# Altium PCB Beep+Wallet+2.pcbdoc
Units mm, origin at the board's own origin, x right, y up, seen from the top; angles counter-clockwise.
Board outline 180.01 x 75.63 mm, 2 copper layers (Top Layer, Bottom Layer); 63 components, 77 nets, 190 pads, 31 vias.
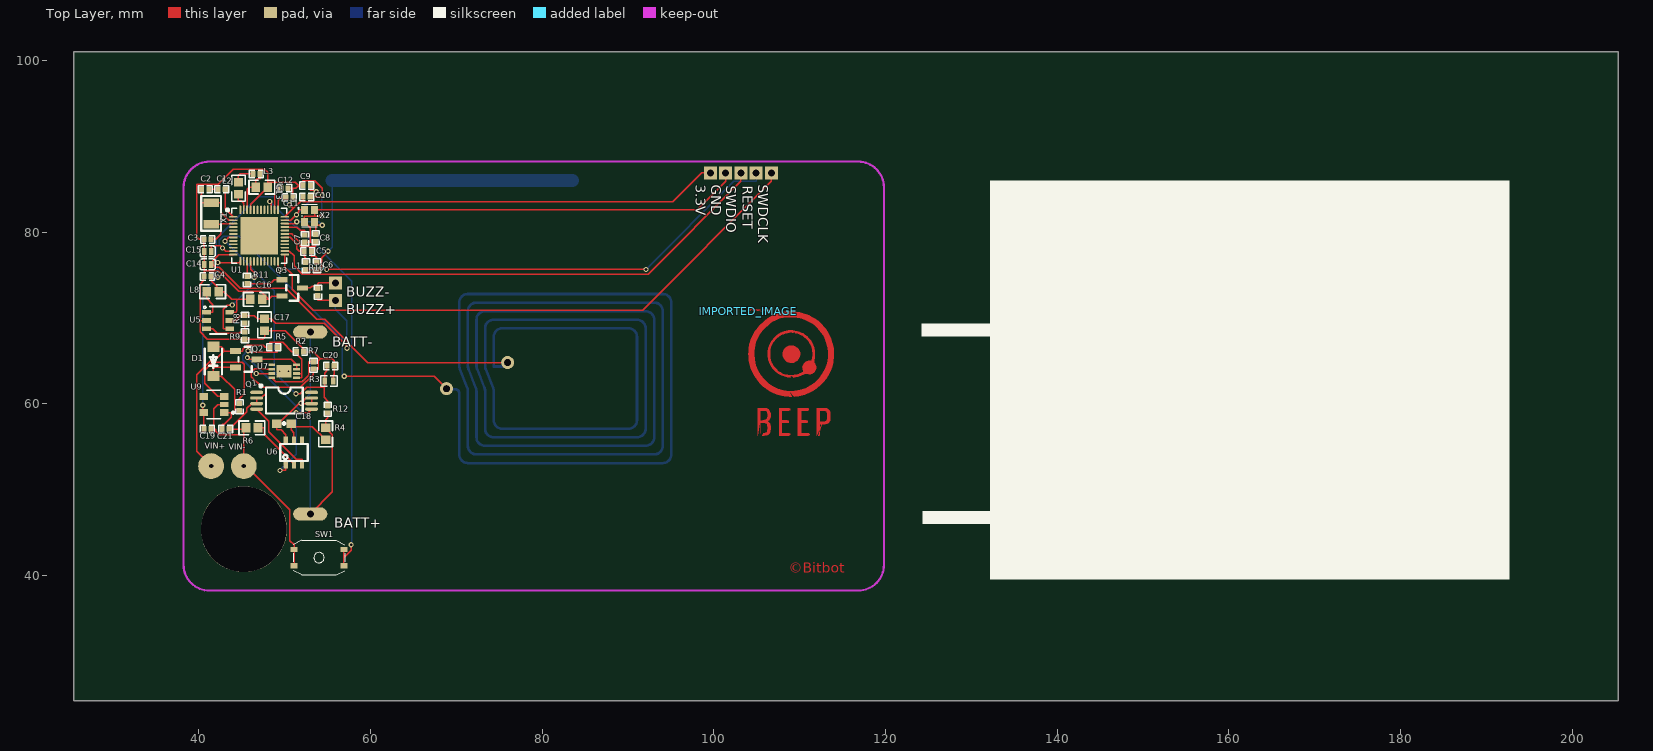
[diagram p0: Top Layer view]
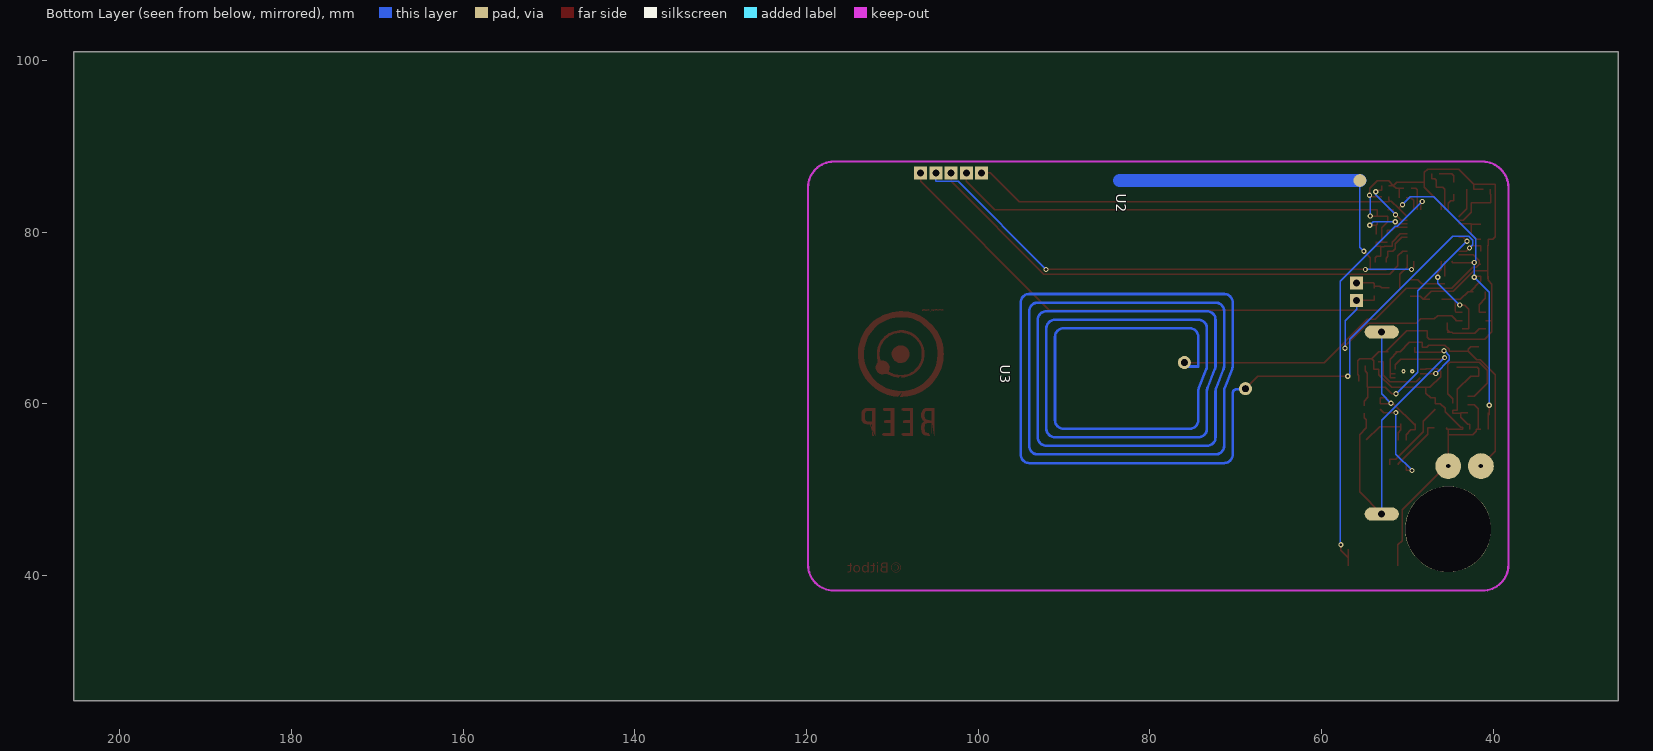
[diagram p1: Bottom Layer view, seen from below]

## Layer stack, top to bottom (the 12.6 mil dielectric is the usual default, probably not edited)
Top Layer: signal copper (thickness not stored)
Dielectric: dielectric 0.32, FR-4, Dk 4.8
Bottom Layer: signal copper (thickness not stored)

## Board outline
205.411,25.4 25.4,25.4 25.4,101.034 205.411,101.034

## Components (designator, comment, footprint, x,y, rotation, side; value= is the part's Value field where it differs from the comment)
3.3V "Pad 04" CON_PAD_SQUARE_32MIL#1 99.596,86.896 r0 top
BATT+ "Pad 09" CON_PAD_SQUARE_32MIL#2 52.987,47.145 r0 top
BATT- "Pad 08" CON_PAD_SQUARE_32MIL#2 52.987,68.354 r0 top
BUZZ+ "Pad 06" CON_PAD_SQUARE_32MIL#1 55.908,72.037 r180 top
BUZZ- "Pad 07" CON_PAD_SQUARE_32MIL#1 55.908,74.069 r180 top
C1 "100nF" 0402 42.657,84.991 r0 top
C2 "12pF" 0402 40.752,84.991 r0 top
C3 "12pF" 0402 41.006,79.149 r180 top
C4 "100nF" 0402 41.006,74.831 r0 top
C5 "0.8pF" 0402 52.69,77.752 r180 top
C6 "1.2pF" 0402 53.749,76.058 r90 top
C7 "100pF" 0402 52.352,79.233 r270 top
C8 "12pF" 0402 53.622,79.319 r90 top
C9 "12pF" 0402 52.578,85.42 r0 top
C10 "100nF" 0402 52.563,84.102 r0 top
C11 "12pF" 0402 50.546,84.023 r180 top
C12 "12pF" 0402 49.982,85.118 r180 top
C13 "1uF" 0603#1 47.334,85.245 r0 top
C14 "300pF" CAP_0402 41.03,76.228 r180 top
C15 "300pF" CAP_0402 41.03,77.752 r0 top
C16 "4.7uF" 0603#1 46.699,72.164 r0 top
C17 "4.7uF" 0603#1 47.653,69.178 r270 top
C18 "0.1UF-25V-5%(0603)" 0603-CAP 49.939,57.686 r0 top
C19 "10pF" 0402 41.006,57.051 r0 top
C20 "10nF" 0402 55.357,64.417 r0 top
C21 "10pF" 0402 43.124,57.051 r0 top
D1 "LMBR120FT1G" SOD-123_L2.8-W1.8-LS3.7-RD 41.684,64.925 r90 top
GND "Pad 05" CON_PAD_SQUARE_32MIL#1 101.374,86.896 r0 top
IMPORTED_IMAGE "IMPORTED_IMAGE" IMPORTED_IMAGE 104.041,70.767 r0 top
L1 "3.9nH" 0402 52.479,76.058 r270 top
L2 "10uH" 0603#1 44.62,85.104 r90 top
L3 "15nH" 0402 46.721,86.769 r0 top
L8 "10uH" 0603#1 41.619,73.053 r0 top
Q1 "FS8205A" TSSOP-8_3X4.4X065P 47.145,61.369 r0 top
Q2 "DMG3415U-7" SOT-23-3_L2.9-W1.6-P1.90-LS2.8-BR-CW 45.515,65.179 r180 top
Q3 "PMBT3904,215" SOT-23_L2.9-W1.3-P0.95-LS2.4-BR 50.885,73.495 r180 top
R1 "100K" 0402 44.732,59.634 r270 top
R2 "100K" 0402 51.801,66.068 r180 top
R3 "4.02M" R0402 55.154,62.639 r0 top
R4 "100Ω(100R)" 0603#2 54.765,55.681 r90 top
R5 "1K" 0402 48.712,66.576 r0 top
R6 "1KΩ" 0603#2 45.391,57.178 r0 top
R7 "1K" 0402 53.368,64.46 r270 top
R8 "1M" 0402 45.367,69.835 r270 top
R9 "29.4K" 0402 45.367,67.93 r90 top
R10 "3.01K" 0402 53.876,73.01 r90 top
R11 "10K" 0402 45.621,74.407 r270 top
R12 "10M" 0402 55.019,59.337 r90 top
RESET "Pad 03" CON_PAD_SQUARE_32MIL#1 104.93,86.896 r0 top
SW1 "SKTKABE010" SKTKABE010 54.003,42.065 r0 top
SWDCLK "Pad 02" CON_PAD_SQUARE_32MIL#1 106.708,86.896 r0 top
SWDIO "Pad 01" CON_PAD_SQUARE_32MIL#1 103.152,86.896 r0 top
U1 "2.4GHz" QFN-48_L6.0-W6.0-P0.40-BL-EP3.8 47.033,79.578 r270 top
U2 "Antenna" ANTENNA 62.639,86.007 r270 bottom
U3 "NFC_Antenna" NFC_ANTENNA 79.784,61.496 r270 bottom
U5 "TLV61046ADBVT" SOT-23-6#1 42.239,69.69 r0 top
U6 "DW01A-G" SOT-23-6#2 51.082,54.308 r0 top
U7 "MCP73831-2ACI/MC" DFN-MC8 49.939,63.782 r180 top
U9 "AP2112K-3.3TRG1" SOT-25_5PIN_L3.10-W3.00-PITCH0.95-BR 41.754,59.906 r0 top
VIN+ "Pad 10" CON_PAD_SQUARE_32MIL#3 41.43,52.733 r0 top
VIN- "Pad 11" CON_PAD_SQUARE_32MIL#3 45.24,52.733 r0 top
X1 "32.768MHz" OSC-SMD_L3.2-W1.5 41.43,82.177 r270 top
X2 "32MHz" OSC-SMD_4P-L2.0-W1.6-BL 52.895,81.878 r270 top

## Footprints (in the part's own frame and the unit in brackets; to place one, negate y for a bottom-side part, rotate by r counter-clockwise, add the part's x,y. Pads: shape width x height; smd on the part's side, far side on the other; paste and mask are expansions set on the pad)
0402 [mm]
  rect 0.6x0.65 smd: 1(-0.424,0) 2(0.424,0)
  silkscreen extent -0.82,-0.43 0.81,0.43
0603#1 [mm]
  rect 1x1.1 smd: 1(-0.7,0) 2(0.7,0)
  silkscreen extent -1.5,-0.8 1.5,0.8
0603#2 [mm]
  rect 1x1.1 smd: 1(0.1,0) 2(1.5,0)
  silkscreen extent -0.7,-0.8 2.3,0.8
0603-CAP [mil]
  rect 43.3x39.4 smd: 1(-33,0) 2(33,0)
  silkscreen extent 0,-1 0,1
ANTENNA [mm]
  round 1.5 smd: 1(0,7.112)
  Top Layer lines w1.5: 0,7.112 0,-20.888
CAP_0402 [mm]
  rect 0.5x0.8 smd: 1(-0.4,0) 2(0.4,0)
  silkscreen extent -0.89,-0.64 0.89,0.64
CON_PAD_SQUARE_32MIL#1 [mil]
  rect 60x60 hole 32: P(0,0)
CON_PAD_SQUARE_32MIL#2 [mil]
  oval 157.48x60 hole 32: P(0,0)
CON_PAD_SQUARE_32MIL#3 [mil]
  round 118.11 hole 19.69: P(0,0)
DFN-MC8 [mil]
  rect 30.5x12.5 smd: 1(-57,29.5) 2(-57,10.5) 3(-57,-9.5) 4(-57,-29.5) 5(57,-29.5) 6(57,-9.5) 7(57,10.5) 8(57,29.5)
  rect 69.5x57.5 smd: 9(0,0.5)
  silkscreen extent -82,44 -82,44
IMPORTED_IMAGE [mm]
  Top Layer region: 1.091,-14.489 1.091,-12.893 1.091,-11.297 1.617,-11.297 1.703,-11.298 1.788,-11.299 1.871,-11.302 1.949,-11.306 2.022,-11.31 2.088,-11.315 2.146,-11.321 2.194,-11.327 2.232,-11.334 2.258,-11.341 2.351,-11.402 2.43,-11.501 2.494,-11.631 2.542,-11.782 2.571,-11.947 2.583,-12.116 2.574,-12.281 2.545,-12.433 2.494,-12.564 2.42,-12.666 2.261,-12.822 2.42,-12.979 2.456,-13.017 2.487,-13.055 2.512,-13.096 2.533,-13.139 2.549,-13.188 2.561,-13.243 2.57,-13.306 2.576,-13.379 2.579,-13.464 2.58,-13.561 2.574,-13.772 2.555,-13.95 2.52,-14.098 2.465,-14.217 2.389,-14.311 2.288,-14.382 2.16,-14.432 2.002,-14.465 1.811,-14.483 1.584,-14.489 1.715,-14.205 1.771,-14.204 1.826,-14.201 1.88,-14.195 1.932,-14.188 1.98,-14.18 2.024,-14.17 2.063,-14.159 2.096,-14.147 2.122,-14.134 2.14,-14.12 2.154,-14.1 2.167,-14.071 2.18,-14.033 2.191,-13.987 2.201,-13.934 2.209,-13.875 2.216,-13.812 2.221,-13.744 2.224,-13.674 2.225,-13.602 2.224,-13.53 2.221,-13.46 2.216,-13.393 2.209,-13.329 2.201,-13.27 2.191,-13.217 2.18,-13.171 2.167,-13.133 2.154,-13.104 2.14,-13.084 2.122,-13.071 2.096,-13.057 2.063,-13.045 2.024,-13.034 1.98,-13.024 1.932,-13.016 1.88,-13.009 1.826,-13.004 1.771,-13 1.715,-12.999 1.374,-12.999 1.374,-13.602 1.374,-14.205 1.374,-12.734 1.693,-12.698 1.746,-12.691 1.799,-12.682 1.852,-12.672 1.902,-12.66 1.95,-12.647 1.994,-12.633 2.034,-12.618 2.069,-12.603 2.097,-12.588 2.119,-12.574 2.155,-12.525 2.183,-12.45 2.205,-12.354 2.219,-12.243 2.225,-12.126 2.224,-12.008 2.215,-11.897 2.198,-11.798 2.173,-11.719 2.14,-11.666 2.122,-11.652 2.096,-11.639 2.063,-11.627 2.024,-11.616 1.98,-11.606 1.932,-11.597 1.88,-11.59 1.826,-11.585 1.771,-11.582 1.715,-11.581 1.374,-11.581 1.374,-12.157 1.374,-12.734
  Top Layer region: 3.573,-14.489 3.573,-12.893 3.573,-11.297 4.211,-11.297 4.373,-11.298 4.504,-11.299 4.61,-11.303 4.691,-11.309 4.752,-11.319 4.795,-11.332 4.823,-11.35 4.84,-11.374 4.847,-11.403 4.849,-11.439 4.848,-11.474 4.841,-11.503 4.827,-11.526 4.804,-11.544 4.77,-11.558 4.722,-11.568 4.658,-11.574 4.577,-11.578 4.476,-11.58 4.353,-11.581 3.856,-11.581 3.856,-12.148 3.856,-12.716 4.282,-12.716 4.386,-12.716 4.472,-12.718 4.541,-12.722 4.595,-12.729 4.637,-12.739 4.667,-12.753 4.687,-12.771 4.7,-12.794 4.706,-12.823 4.708,-12.857 4.706,-12.892 4.7,-12.921 4.687,-12.944 4.667,-12.962 4.637,-12.976 4.595,-12.986 4.541,-12.992 4.472,-12.997 4.386,-12.999 4.282,-12.999 3.856,-12.999 3.856,-13.602 3.856,-14.205 4.353,-14.205 4.476,-14.205 4.577,-14.207 4.658,-14.211 4.722,-14.218 4.77,-14.228 4.804,-14.241 4.827,-14.259 4.841,-14.283 4.848,-14.312 4.849,-14.347 4.847,-14.383 4.84,-14.412 4.823,-14.435 4.795,-14.453 4.752,-14.467 4.691,-14.476 4.61,-14.483 4.504,-14.486 4.373,-14.488 4.211,-14.489
  Top Layer region: 5.771,-14.489 5.771,-12.893 5.771,-11.297 6.41,-11.297 6.571,-11.298 6.703,-11.299 6.808,-11.303 6.89,-11.309 6.95,-11.319 6.994,-11.332 7.022,-11.35 7.038,-11.374 7.046,-11.403 7.048,-11.439 7.046,-11.474 7.04,-11.503 7.027,-11.526 7.005,-11.544 6.973,-11.558 6.928,-11.567 6.869,-11.574 6.794,-11.578 6.7,-11.58 6.587,-11.581 6.126,-11.581 6.126,-12.148 6.126,-12.716 6.516,-12.716 6.61,-12.716 6.688,-12.718 6.751,-12.723 6.801,-12.73 6.84,-12.74 6.868,-12.754 6.887,-12.772 6.898,-12.795 6.904,-12.823 6.906,-12.857 6.904,-12.892 6.898,-12.92 6.887,-12.943 6.868,-12.961 6.84,-12.975 6.801,-12.985 6.751,-12.992 6.688,-12.996 6.61,-12.999 6.516,-12.999 6.126,-12.999 6.126,-13.602 6.126,-14.205 6.622,-14.205 6.745,-14.205 6.847,-14.207 6.928,-14.211 6.991,-14.218 7.039,-14.228 7.074,-14.241 7.097,-14.259 7.11,-14.283 7.117,-14.312 7.119,-14.347 7.117,-14.383 7.109,-14.412 7.092,-14.436 7.062,-14.454 7.017,-14.467 6.953,-14.477 6.867,-14.483 6.756,-14.486 6.616,-14.488 6.445,-14.489
  Top Layer region: 7.97,-14.489 7.97,-12.893 7.97,-11.297 8.576,-11.297 8.727,-11.298 8.853,-11.3 8.957,-11.305 9.042,-11.313 9.113,-11.325 9.172,-11.342 9.222,-11.364 9.267,-11.393 9.311,-11.428 9.356,-11.471 9.399,-11.516 9.434,-11.559 9.463,-11.604 9.485,-11.654 9.502,-11.711 9.514,-11.778 9.522,-11.86 9.527,-11.959 9.53,-12.077 9.53,-12.219 9.53,-12.361 9.527,-12.479 9.522,-12.578 9.514,-12.66 9.502,-12.727 9.485,-12.784 9.463,-12.834 9.434,-12.879 9.399,-12.922 9.356,-12.967 9.313,-13.007 9.272,-13.041 9.23,-13.069 9.185,-13.092 9.135,-13.109 9.079,-13.122 9.015,-13.131 8.94,-13.137 8.854,-13.14 8.753,-13.141 8.325,-13.141 8.325,-13.815 8.324,-13.997 8.323,-14.143 8.32,-14.256 8.313,-14.342 8.302,-14.403 8.286,-14.445 8.263,-14.47 8.234,-14.483 8.195,-14.488 8.147,-14.489 8.665,-12.857 8.721,-12.856 8.777,-12.853 8.831,-12.848 8.882,-12.841 8.93,-12.832 8.974,-12.822 9.013,-12.811 9.046,-12.799 9.072,-12.786 9.091,-12.772 9.105,-12.752 9.118,-12.722 9.131,-12.682 9.142,-12.634 9.151,-12.578 9.16,-12.516 9.167,-12.448 9.171,-12.375 9.175,-12.299 9.176,-12.219 9.175,-12.139 9.171,-12.063 9.167,-11.99 9.16,-11.922 9.151,-11.86 9.142,-11.804 9.131,-11.756 9.118,-11.716 9.105,-11.686 9.091,-11.666 9.072,-11.652 9.046,-11.639 9.013,-11.627 8.974,-11.616 8.93,-11.606 8.882,-11.597 8.831,-11.59 8.777,-11.585 8.721,-11.582 8.665,-11.581 8.325,-11.581 8.325,-12.219 8.325,-12.857 8.665,-12.857
  Top Layer region: 162 vertices and 0 holes, not listed, extent 0,-9.947 9.946,-0.002
  Top Layer region: 214 vertices and 0 holes, not listed, extent 2.24,-7.729 7.892,-2.216
  Top Layer region: 5.056,-6.017 4.947,-6.012 4.835,-5.993 4.721,-5.961 4.603,-5.915 4.49,-5.858 4.388,-5.793 4.297,-5.719 4.219,-5.637 4.152,-5.547 4.097,-5.45 4.054,-5.345 4.024,-5.232 4.005,-5.112 3.999,-4.985 4.004,-4.879 4.018,-4.777 4.042,-4.679 4.076,-4.586 4.118,-4.497 4.17,-4.413 4.231,-4.334 4.302,-4.26 4.381,-4.191 4.469,-4.127 4.509,-4.103 4.552,-4.082 4.6,-4.062 4.65,-4.045 4.704,-4.029 4.759,-4.017 4.816,-4.007 4.875,-3.999 4.933,-3.994 4.991,-3.993 5.266,-4.025 5.504,-4.114 5.703,-4.252 5.858,-4.428 5.966,-4.633 6.023,-4.857 6.026,-5.091 5.97,-5.324 5.853,-5.548 5.669,-5.752 5.57,-5.831 5.471,-5.896 5.37,-5.947 5.267,-5.984 5.163,-6.007
NFC_ANTENNA [mil]
  round 60 hole 30 slot 30.2 at 0 deg: 1(-10,430) 2(-130,150)
  Top Layer lines w11.81: -12.07,427.81 cw(c-24.99,414.89) -6.72,414.9 -6.72,414.31 -6.72,392.82 -6.72,389.05 ccw(c11,389.05) 11,371.33 289.74,371.33 291.72,371.33 cw(c291.72,331.97) 331.08,331.97 331.08,-561.74 cw(c291.72,-561.74) 291.72,-601.1 -405.14,-601.11 cw(c-405.14,-561.74) -444.51,-561.74 -444.51,331.97 cw(c-405.15,331.97) -405.15,371.33 -114.19,371.33 -113.15,371.33 -110.41,371.16 -107.69,370.8 -104.99,370.25 -102.35,369.52 -99.76,368.6 -13.67,334.7 ; -13.99,334.84 ccw(c0.77,371.34) 0.76,331.97 252.34,331.97 cw(c252.34,292.6) 291.71,292.6 291.71,-522.37 ; -13.99,295.46 ccw(c0.77,331.96) 0.76,292.59 212.97,292.59 cw(c212.97,253.22) 252.34,253.22 252.34,-483 cw(c212.97,-482.99) 212.97,-522.36 ; -13.67,295.33 -99.76,329.23 -102.35,330.15 -104.99,330.88 -107.69,331.43 -110.41,331.79 -113.15,331.96 -114.19,331.97 -365.77,331.97 ccw(c-365.77,292.6) -405.14,292.6 ; -13.99,256.09 ccw(c0.77,292.59) 0.76,253.22 173.6,253.22 cw(c173.6,213.85) 212.97,213.85 212.97,-443.63 cw(c173.6,-443.62) 173.6,-482.99 -287.03,-483 cw(c-287.03,-443.63) -326.4,-443.63 -326.4,213.85 cw(c-287.03,213.85) -287.03,253.22 -114.19,253.22 -113.15,253.22 -110.41,253.05 -107.69,252.69 -104.99,252.14 -102.35,251.41 -99.76,250.49 -13.67,216.59 ; -13.67,255.96 -99.76,289.86 -102.35,290.78 -104.99,291.51 -107.69,292.06 -110.41,292.42 -113.15,292.59 -114.19,292.59 -326.4,292.59 ccw(c-326.4,253.22) -365.77,253.22 -365.77,-483 ccw(c-326.4,-483) -326.4,-522.37 212.97,-522.37 ; -13.99,216.72 ccw(c0.77,253.22) 0.76,213.85 134.23,213.85 cw(c134.23,174.48) 173.6,174.48 173.6,-404.26 cw(c134.23,-404.25) 134.23,-443.62 -247.66,-443.63 cw(c-247.66,-404.26) -287.03,-404.26 -287.03,174.48 cw(c-247.66,174.48) -247.66,213.85 -111.83,213.85 -111.83,168.17 -130,150 ; 291.71,-522.36 291.71,-522.37 ; -405.14,292.6 -405.14,292.59 ; -405.14,292.59 -405.14,-522.37 ccw(c-365.77,-522.37) -365.77,-561.74 252.34,-561.74 ccw(c252.34,-522.37) 291.71,-522.37
OSC-SMD_4P-L2.0-W1.6-BL [mm]
  rect 0.9x0.8 smd: 1(-0.7,-0.6) 2(0.7,-0.6) 3(0.7,0.6) 4(-0.7,0.6)
  silkscreen extent -1.3,-1.37 1.3,0.9
OSC-SMD_L3.2-W1.5 [mm]
  rect 1x1.8 smd: 1(-1.25,0) 2(1.25,0)
  silkscreen extent -2.03,-1.14 2.03,1.14
QFN-48_L6.0-W6.0-P0.40-BL-EP3.8 [mm]
  oval 0.22x1 smd: 1(-2.201,-3) 2(-1.8,-3) 3(-1.401,-3) 4(-0.999,-3) 5(-0.601,-3) 6(-0.199,-3) 7(0.199,-3) 8(0.601,-3) 9(0.999,-3) 10(1.401,-3) 11(1.8,-3) 12(2.201,-3) 25(2.201,3) 26(1.8,3) 27(1.401,3) 28(0.999,3) 29(0.601,3) 30(0.199,3) 31(-0.199,3) 32(-0.601,3) 33(-0.999,3) 34(-1.401,3) 35(-1.8,3) 36(-2.201,3)
  oval 1x0.22 smd: 13(3,-2.198) 14(3,-1.8) 15(3,-1.401) 16(3,-0.999) 17(3,-0.601) 18(3,-0.199) 19(3,0.199) 20(3,0.601) 21(3,0.999) 22(3,1.401) 23(3,1.8) 24(3,2.201) 37(-3,2.201) 38(-3,1.8) 39(-3,1.401) 40(-3,0.999) 41(-3,0.601) 42(-3,0.199) 43(-3,-0.199) 44(-3,-0.601) 45(-3,-0.999) 46(-3,-1.401) 47(-3,-1.8) 48(-3,-2.198)
  rect 4.4x4.4 smd: 49(-0.001,0.001)
  silkscreen extent -3.2,-3.85 3.2,3.2
R0402 [mm]
  rect 0.5x0.8 smd: 1(-0.5,0) 2(0.5,0)
  silkscreen extent -0.95,-0.6 0.95,0.6
SKTKABE010 [mm]
  rect 0.8x0.6 smd: 1(-2.9,0.95) 2(-2.9,-0.95) 3(2.9,-0.95) 4(2.9,0.95)
  silkscreen extent -3,-2 3,2
SOD-123_L2.8-W1.8-LS3.7-RD [mm]
  rect 1.2x1.4 smd: 1(-1.7,0) 2(1.7,0)
  silkscreen extent -1.5,-1 1.5,1
SOT-23-3_L2.9-W1.6-P1.90-LS2.8-BR-CW [mm]
  rect 1.25x0.7 smd: 1(1.25,-0.95) 2(-1.25,0) 3(1.25,0.95)
  silkscreen extent -0.65,-1.46 0.9,1.46
SOT-23-6#1 [mm]
  rect 1x0.55 smd: 1(-1.35,0.95) 2(-1.35,0) 3(-1.35,-0.95) 4(1.35,-0.95) 5(1.35,0) 6(1.35,0.95)
  silkscreen extent -1.67,-1.56 1.01,1.67
SOT-23-6#2 [mm]
  rect 0.511x0.8 smd: 1(-0.94,-1.448) 2(0,-1.448) 3(0.94,-1.448) 4(0.94,1.448) 5(0,1.448) 6(-0.94,1.448)
  silkscreen extent -1.6,-0.99 1.6,0.99
SOT-23_L2.9-W1.3-P0.95-LS2.4-BR [mm]
  rect 1.3x0.6 smd: 1(1.2,-0.95) 2(1.2,0.95) 3(-1.2,0)
  silkscreen extent -0.7,-1.5 0.7,1.5
SOT-25_5PIN_L3.10-W3.00-PITCH0.95-BR [mm]
  rect 1x0.8 smd: 1(1.2,-0.95) 3(1.2,0.95) 4(-1.2,0.95) 5(-1.2,-0.95)
  rect 1x0.6 smd: 2(1.2,0)
  silkscreen extent -0.8,-1.65 2.38,1.65
TSSOP-8_3X4.4X065P [mm]
  oval 1.5x0.4 smd: 1(-0.406,-0.051) 2(-0.406,-0.701) 3(-0.406,-1.351) 4(-0.406,-2.002) 5(5.994,-2.002) 6(5.994,-1.351) 7(5.994,-0.701) 8(5.994,-0.051)
  silkscreen extent -0.07,-2.51 4.95,0.86

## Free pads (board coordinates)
  round 10 hole 10 unplated: ""(45.24,45.367)

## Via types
v1: diameter 0.61, hole 0.31, Top Layer to Bottom Layer, 29 vias
v2: diameter 0.5, hole 0.201, Top Layer to Bottom Layer, 2 vias

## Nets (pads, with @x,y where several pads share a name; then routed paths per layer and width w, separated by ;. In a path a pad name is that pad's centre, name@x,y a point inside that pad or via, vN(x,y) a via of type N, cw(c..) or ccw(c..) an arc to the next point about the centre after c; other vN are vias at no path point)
3.3V: 3.3V.P C4.2 C10.1 C16.1 C19.1 L8.2 U1.13 U1.36 U5.6 U9.5 | length 99.4
  Top Layer w0.16: v1(40.452,59.832) 40.452,58.735 U9.5@40.554,58.634 ; U9.5 U9.5@40.554,58.634 ; C19.1 40.582,58.286 40.554,58.313 U9.5@40.554,58.634 ; v1(42.205,74.73) 42.103,74.831 41.974,74.831 C4.2 41.43,74.265 41.478,74.265 L8.2@42.69,73.053 ; v1(42.205,76.444) 44.694,76.444 U1.13@44.836,76.586 ; L8.2 L8.2@42.69,73.053 ; U5.6 44.331,70.64 44.443,70.752 44.443,72.164 ; C16.1 44.443,72.164 ; U1.36@50.026,81.778 50.998,82.751 ; v1(50.572,83.178) 50.998,82.751 ; C10.1 52.139,83.769 52.08,83.711 52.08,83.609 ; 3.3V.P 98.593,86.896 95.212,83.515 52.174,83.515 52.08,83.609 ; L8.2@42.69,73.053 42.929,73.053 43.818,72.164 44.443,72.164 ; 50.998,82.751 51.857,83.609 52.08,83.609
  Bottom Layer w0.16: v1(40.452,59.832) 40.452,72.977 v1(42.205,74.73) v1(42.205,76.444) 42.012,76.637 42.012,79.192 46.929,84.11 49.639,84.11 v1(50.572,83.178)
BAT: C20.1 R3.1 R12.2 U1.7 | length 30.9
  Top Layer w0.16: v1(43.053,78.928) 43.503,79.378 U1.7@44.026,79.378 ; v1(51.313,61.168) 51.814,61.168 52.578,61.93 54.59,61.93 ; C20.1 54.933,64.133 54.933,63.851 54.653,63.571 R3.1 54.653,62.012 54.653,61.996 54.59,61.93 ; R12.2 55.019,60.302 54.59,60.734 54.59,61.93
  Bottom Layer w0.16: v1(43.053,78.928) 48.801,73.18 48.801,63.681 v1(51.313,61.168)
BUTTON: SW1.3 SW1.4 U1.39 | length 48.9
  Top Layer w0.16: v1(48.268,83.564) 48.436,83.396 U1.39@48.436,82.586 ; SW1.3 56.904,42.065 ; SW1.4 56.904,42.065 ; v1(57.74,43.564) 57.74,42.903 56.904,42.065
  Bottom Layer w0.16: v1(48.268,83.564) 51.169,80.663 51.387,80.663 57.808,74.242 57.808,43.63 v1(57.74,43.564)
BUZZ: R11.1 U1.15 | length 1.8
  Top Layer w0.16: R11.1 45.621,75.372 45.634,75.385 U1.15@45.634,76.586
BUZZ+: BUZZ+.P C17.1 R8.1 R10.1 U5.5 | length 24.4
  Top Layer w0.16: U5.5 44.331,69.69 44.331,69.792 44.801,70.259 R8.1 46.48,70.259 46.861,69.878 C17.1 48.446,69.878 48.944,69.38 54.628,69.38 57.259,66.746 v1(57.259,66.472) ; R10.1 53.876,72.042 53.884,72.037 BUZZ+.P
  Bottom Layer w0.16: BUZZ+.P 55.908,71.034 57.259,69.68 v1(57.259,66.472)
BUZZ-: BUZZ-.P Q3.3 R10.2 | length 4.5
  Top Layer w0.16: Q3.3 52.977,73.495 53.188,73.706 R10.2@53.876,73.706 ; R10.2 R10.2@53.876,73.706 ; BUZZ-.P 53.97,74.069 53.876,73.975 R10.2@53.876,73.706
BUZZEN: U1.16 U5.4 | length 10.6
  Top Layer w0.16: U5.4 42.848,68.74 42.848,71.013 43.33,71.499 v1(43.897,71.499) ; U1.16@46.035,76.586 46.035,75.679 46.449,75.263 v1(46.449,74.742)
  Bottom Layer w0.16: v1(43.897,71.499) 46.449,74.054 v1(46.449,74.742)
GND: C1.1 C2.2 C3.2 C4.1 C5.1 C6.2 C7.2 C8.1 C9.1 C10.2 C11.1 C12.1 C13.2 C14.2 C15.1 C16.2 C17.2 C19.2 C20.2 C21.2 GND.P Q1.2 Q1.3 Q3.2 R2.1 R3.2 R6.1 R7.2 R9.1 SW1.1 SW1.2 U1.31 U1.45 U5.2 U7.6 U9.2 VIN-.P X2.2 X2.4 | length 197.2
  Top Layer w0.16: C4.1 C4.1@40.582,74.547 ; U5.2 40.147,69.69 ; C2.2 C1.1 42.233,85.558 ; C19.2 41.743,57.051 ; U9.2 42.213,59.906 41.743,59.436 41.743,57.051 ; R6.1 45.365,57.051 R6.1@45.24,57.051 ; U1.45@46.035,82.586 46.035,83.246 C13.2 48.034,85.827 ; C16.2 48.141,72.164 ; U7.6 47.861,64.023 47.803,64.084 46.49,64.084 46.134,63.729 46.134,63.147 47.386,61.895 47.861,61.895 ; Q3.2 48.522,72.545 48.141,72.164 ; U1.31@50.026,79.776 50.828,79.776 51.786,78.821 51.786,78.367 51.834,78.319 52.667,78.319 52.69,78.293 53.114,78.293 ; C12.1 50.678,85.118 50.97,85.118 ; C11.1 50.97,84.308 50.97,84.59 50.97,85.118 ; SW1.2 SW1.1 51.103,43.556 50.605,44.056 50.605,47.653 45.525,52.733 VIN-.P 45.24,56.388 ; C9.1 51.613,85.42 ; R2.1 R2.1@52.497,66.068 ; C7.2 52.987,78.809 ; C10.2 53.531,84.102 54.204,84.102 v1(54.405,84.3) 54.405,85.103 53.521,85.987 52.179,85.987 51.613,85.42 ; C8.1 C8.1@53.622,78.809 ; C6.2 53.749,77.023 53.589,77.186 53.114,77.186 C5.1 53.114,78.037 53.114,78.237 53.114,78.293 ; v1(54.321,81.869) 53.495,81.869 ; R3.2 55.654,63.282 55.781,63.409 C20.2 55.781,64.984 55.55,65.215 54.166,65.215 ; GND.P 101.374,85.893 98.059,82.578 X2.4 53.495,81.869 ; 40.147,69.69 40.147,73.922 40.582,74.359 C4.1@40.582,74.547 ; 40.147,69.69 40.147,68.364 41.006,67.506 R9.1 47.422,67.506 47.653,67.737 C17.2 50.087,68.479 R2.1@52.497,66.068 ; C4.1@40.582,74.547 40.63,74.595 40.63,75.492 ; 40.63,75.492 42.248,75.492 44.623,73.117 47.188,73.117 48.141,72.164 ; 40.63,75.492 C14.2 C15.1 40.63,78.395 40.582,78.443 C3.2 40.041,79.149 39.749,79.441 39.749,85.512 39.794,85.558 42.233,85.558 ; 41.743,57.051 41.974,57.051 41.974,56.779 42.365,56.388 45.24,56.388 ; 42.233,85.558 44.011,87.336 47.64,87.336 48.034,86.944 48.034,85.827 ; 45.24,56.388 R6.1@45.24,57.051 ; R6.1@45.24,57.051 C21.2 43.549,57.262 43.782,57.262 45.601,59.081 45.601,59.446 46.175,60.018 Q1.3 Q1.2 47.282,60.668 47.861,61.247 47.861,61.895 ; 47.861,61.895 51.829,61.895 53.307,63.373 53.307,64.036 53.338,64.036 R7.2 53.935,64.036 53.935,64.984 54.166,65.215 ; 48.034,85.827 51.207,85.827 51.613,85.42 ; 50.97,85.118 51.311,85.118 51.613,85.42 ; R2.1@52.497,66.068 53.315,66.068 54.166,65.215 ; 52.987,78.809 52.987,80.485 X2.2 52.296,81.374 52.296,81.869 53.495,81.869 ; 52.987,78.809 C8.1@53.622,78.809 ; 53.114,78.293 53.173,78.352 53.622,78.352 C8.1@53.622,78.809
  Bottom Layer w0.16: v1(54.321,81.869) 54.321,84.219 v1(54.405,84.3)
L1_2: C6.1 L1.2 U2.1 | length 40.7
  Top Layer w0.16: L1.2 C6.1 54.316,75.634 54.316,77.031 v1(55.06,77.775)
  Bottom Layer w0.16: v1(55.06,77.775) 55.527,78.242 U2.1 83.528,86.007
L2_2: L2.2 L3.1 | length 2.5
  Top Layer w0.16: L2.2 44.62,86.546 44.844,86.769 L3.1
NFC1: C15.2 U1.11 U3.1 | length 41
  Top Layer w0.16: C15.2 41.43,78.395 42.502,78.395 v1(42.761,78.133) 43.117,77.778 U1.11@44.026,77.778 ; v1(56.939,63.211) 67.402,63.211 U3.1
  Bottom Layer w0.16: v1(42.761,78.133) 42.388,78.506 42.388,79.07 42.82,79.502 44.714,79.502 56.713,67.506 56.713,63.439 v1(56.939,63.211)
NFC2: C14.1 U1.12 U3.2 | length 49.2
  Top Layer w0.16: C14.1 C14.1@41.623,76.228 ; U1.12@44.026,77.376 42.329,77.376 41.623,76.67 C14.1@41.623,76.228 ; U3.2 59.708,64.798 54.692,69.817 53.734,69.817 50.109,73.439 44.831,73.439 42.375,75.895 41.956,75.895 C14.1@41.623,76.228
  Bottom Layer w0.16: 75.352,68.786 75.314,68.786 75.268,68.783 75.225,68.778 75.179,68.771 75.136,68.763 75.093,68.753 75.05,68.74 75.006,68.725 74.963,68.707 74.923,68.689 74.882,68.669 74.844,68.646 74.806,68.623 74.768,68.598 74.732,68.57 74.697,68.542 74.664,68.512 74.633,68.481 74.603,68.446 74.572,68.413 74.544,68.377 74.519,68.339 74.496,68.301 74.473,68.263 74.453,68.222 74.435,68.181 74.417,68.138 74.402,68.098 74.389,68.054 74.379,68.011 74.369,67.965 74.361,67.922 74.356,67.877 74.354,67.831 74.354,67.788 74.354,64.336 75.512,64.336 U3.2
null: 
Q3_1: Q3.1 R11.2 | length 4.3
  Top Layer w0.16: R11.2 48.331,73.983 48.794,74.445 Q3.1
RESET: RESET.P U1.24 | length 61.7
  Top Layer w0.16: U1.24@49.236,76.586 49.236,75.926 v1(49.518,75.644) ; v1(54.885,75.641) v1(92.103,75.641)
  Bottom Layer w0.16: v1(49.518,75.644) 49.52,75.641 v1(54.885,75.641) ; v1(92.103,75.641) 102.355,85.893 104.93,85.893 RESET.P
S$48: 
S$50: 
S$52: 
S$54: 
S$56: 
S$58: 
S$60: 
S$62: 
S$67: 
S$69: 
SWDCLK: SWDCLK.P U1.25 | length 68.4
  Top Layer w0.16: U1.25@50.026,77.376 50.026,75.911 50.876,75.06 50.876,73.358 53.34,70.897 91.712,70.897 106.708,85.893 SWDCLK.P
SWDIO: SWDIO.P U1.26 | length 60.4
  Top Layer w0.16: U1.26@50.026,77.778 50.534,77.778 51.092,77.221 51.092,76.048 52.047,75.09 92.352,75.09 103.152,85.893 SWDIO.P
U1_1: C1.2 U1.1 | length 3.6
  Top Layer w0.16: C1.2 43.081,82.723 U1.1@44.026,81.778
U1_2: C2.1 U1.2 X1.1 | length 6.8
  Top Layer w0.16: C2.1 40.328,84.425 40.287,84.384 40.287,83.426 X1.1 42.573,83.426 42.573,82.283 43.48,81.377 U1.2@44.026,81.377
U1_3: C3.1 U1.3 X1.2 | length 5.2
  Top Layer w0.16: C3.1 41.974,79.149 42.573,79.749 42.573,80.927 ; X1.2 42.573,80.927 ; U1.3@44.026,80.978 42.624,80.978 42.573,80.927
U1_4: U1.4
U1_5: U1.5
U1_6: U1.6
U1_8: U1.8
U1_9: U1.9
U1_10: U1.10
U1_14: U1.14
U1_17: U1.17
U1_18: U1.18
U1_19: U1.19
U1_20: U1.20
U1_21: U1.21
U1_22: U1.22
U1_23: U1.23
U1_27: U1.27
U1_28: U1.28
U1_29: U1.29
U1_30: C5.2 L1.1 U1.30 | length 4.6
  Top Layer w0.16: U1.30@50.026,79.378 50.64,79.378 51.402,78.616 51.402,78.075 51.725,77.752 C5.2 52.266,77.468 52.266,77.186 52.426,77.023 52.479,77.023 L1.1
U1_32: U1.32
U1_33: C7.1 U1.33 | length 3
  Top Layer w0.16: U1.33@50.026,80.577 51.433,80.577 51.811,80.198 52.352,80.198 C7.1
U1_34: C8.2 U1.34 X2.3 | length 6.9
  Top Layer w0.16: U1.34@50.026,80.978 51.176,80.978 v1(51.407,81.209) ; X2.3 53.495,80.932 X2.3@53.622,80.805 ; C8.2 53.622,79.876 53.622,79.891 53.622,80.284 X2.3@53.622,80.805 ; v1(54.384,80.805) X2.3@53.622,80.805
  Bottom Layer w0.16: v1(51.407,81.209) 53.98,81.209 v1(54.384,80.805)
U1_35: C9.2 U1.35 X2.1 | length 7.9
  Top Layer w0.16: U1.35@50.026,81.377 50.681,81.377 v1@51.346,82.042 ; v1(51.372,82.017) v1@51.346,82.042 ; X2.1 51.654,82.578 51.654,82.35 v1@51.346,82.042 ; C9.2 53.002,84.854 53.543,84.854 v1(53.693,84.702)
  Bottom Layer w0.16: v1(51.372,82.017) 53.693,84.338 v1(53.693,84.702)
U1_37: C11.2 U1.37 | length 2.1
  Top Layer w0.16: U1.37@49.236,82.586 49.236,83.678 49.581,84.023 C11.2
U1_38: C12.2 U1.38 | length 3.1
  Top Layer w0.16: U1.38@48.834,82.586 48.834,84.935 49.017,85.118 C12.2
U1_40: U1.40
U1_41: U1.41
U1_42: U1.42
U1_43: U1.43
U1_44: U1.44
U1_46: C13.1 L3.2 U1.46 | length 5.4
  Top Layer w0.16: U1.46@45.634,82.586 45.634,84.986 45.893,85.245 C13.1 46.635,86.038 46.8,86.203 47.145,86.203 L3.2
U1_47: L2.1 U1.47 | length 2.3
  Top Layer w0.16: L2.1 44.62,83.663 44.928,83.663 45.235,83.355 U1.47@45.235,82.586
U1_48: U1.48
U1_49: U1.49
U5_1: L8.1 U5.1 | length 3.4
  Top Layer w0.16: U5.1 41.631,70.64 41.631,71.547 40.92,72.261 L8.1
U5_3: R8.2 R9.2 U5.3 | length 5.9
  Top Layer w0.16: U5.3 41.631,68.74 42.149,68.222 44.669,68.222 44.801,68.354 R9.2@45.083,68.354 ; R9.2 R9.2@45.083,68.354 ; R8.2 45.367,68.639 R9.2@45.083,68.354
U6_1: Q1.5 U6.1 | length 10.8
  Top Layer w0.16: v1(49.454,52.217) 50.142,52.217 U6.1 ; v1(51.336,58.961) 52.733,58.961 Q1.5
  Bottom Layer w0.16: v1(49.454,52.217) 51.336,54.1 v1(51.336,58.961)
U6_2: R6.2 U6.2 | length 6.5
  Top Layer w0.16: R6.2 47.633,57.178 47.633,56.436 51.082,52.987 U6.2
U6_3: Q1.4 U6.3 | length 9.1
  Top Layer w0.16: Q1.4 48.136,57.971 48.136,56.741 51.374,53.503 52.022,53.503 U6.3
U6_5: C18.2 R4.1 U6.5 | length 6.7
  Top Layer w0.16: C18.2 C18.2@50.777,57.315 ; U6.5 51.082,56.64 50.777,56.944 C18.2@50.777,57.315 ; R4.1 53.231,57.315 C18.2@50.777,57.315
U6_6: BATT-.P C18.1 Q1.6 Q1.7 U6.6 | length 18.6
  Top Layer w0.16: C18.1 C18.1@49.101,57.46 ; U6.6 50.142,56.398 49.596,56.944 49.101,56.944 C18.1@49.101,57.46 ; v1(51.913,60.064) 52.517,60.668 Q1.7 Q1.6 51.618,60.018 49.101,57.501 C18.1@49.101,57.46
  Bottom Layer w0.16: v1(51.913,60.064) 52.987,61.138 BATT-.P
U7_7: R5.2 U7.7 | length 9.4
  Top Layer w0.16: v1(45.728,66.157) 45.875,66.01 49.137,66.01 R5.2 ; v1(46.696,63.515) U7.7
  Bottom Layer w0.16: v1(45.728,66.157) 45.649,66.157 45.108,65.616 45.108,65.103 v1(46.696,63.515)
U7_8: R7.1 U7.8 | length 6.9
  Top Layer w0.16: U7.8 48.951,62.573 52.052,62.573 52.802,63.322 52.802,64.884 R7.1
U7_9: U7.9
U9_1: C21.1 D1.1 Q2.3 R1.2 U9.1 | length 14.2
  Top Layer w0.16: C21.1 42.7,57.618 42.987,57.618 43.77,58.402 43.77,58.882 ; U9.1 43.696,58.956 43.77,58.882 ; Q2.3 41.847,64.229 41.684,64.067 41.684,63.645 D1.1 42.627,63.226 44.166,61.687 44.166,59.21 R1.2 44.732,58.882 43.77,58.882
U9_3: R1.1 U9.3 | length 14.2
  Top Layer w0.16: U9.3 42.213,60.856 40.714,62.355 40.714,63.922 41.613,64.821 45.032,64.821 45.268,64.585 45.268,61.135 44.732,60.599 R1.1
VBAT: BATT+.P Q2.2 R4.2 R12.1 U7.3 U7.4 | length 41.1
  Top Layer w0.16: v1(45.657,65.372) 45.702,65.372 45.898,65.179 Q2.2 50.739,65.179 U7.4 U7.3 ; BATT+.P 55.558,49.716 55.558,56.388 R4.2 54.765,58.115 55.019,58.369 R12.1
  Bottom Layer w0.16: v1(45.657,65.372) 45.697,65.372 52.987,58.082 BATT+.P
VIN: D1.2 Q2.1 R2.2 R5.1 U7.1 U7.2 VIN+.P | length 31.9
  Top Layer w0.16: VIN+.P 39.731,54.432 39.731,63.396 41.481,65.146 41.938,65.146 42.921,66.129 ; D1.2 42.627,66.624 42.921,66.33 42.921,66.129 ; R2.2 R2.2@51.148,66.068 ; U7.1 52.017,63.033 52.017,63.515 ; U7.2 52.017,63.515 ; 42.921,66.129 Q2.1 45.134,66.129 45.134,66.345 45.614,66.825 47.496,66.825 47.747,66.576 R5.1 48.288,67.143 49.759,67.143 50.836,66.068 R2.2@51.148,66.068 ; R2.2@51.148,66.068 52.017,65.199 52.017,63.515
pads on no net: Q1.1 Q1.8 U6.4 U7.5 U9.4
copper on no net:
  other v2: 49.439,63.769 50.44,63.769

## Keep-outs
Keep-Out Layer:
  lines w0.254: 38.227,41.217 ccw(c41.227,41.217) 41.227,38.217 ; 38.227,85.207 cw(c41.227,85.207) 41.227,88.207 ; 116.827,38.227 ccw(c116.827,41.227) 119.827,41.227 ; 116.827,88.207 cw(c116.827,85.207) 119.827,85.207

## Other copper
Top Layer:
  text "©Bitbot" at 108.74,39.906 h2.03

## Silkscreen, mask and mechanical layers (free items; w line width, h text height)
Top Overlay:
  rectangle: 132.211,39.516 192.711,86.016
  rectangle: 124.23,67.85 132.23,69.35
  rectangle: 124.294,45.994 132.294,47.494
